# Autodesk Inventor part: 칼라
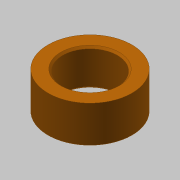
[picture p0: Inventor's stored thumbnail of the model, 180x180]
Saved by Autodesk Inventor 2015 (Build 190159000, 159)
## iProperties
Created: 2015-09
Part Number: 칼라
Document SubType Name: Modeling
Designer: mduedu
Density: 1 g/cm^3
Material: 스테인리스강
Appearance: 주황색
Author: mduedu
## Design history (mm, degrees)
node "작업 평면1"
node "작업 평면2"
sketch "스케치1"
  geometry: C1 r 7.5 at (0, 0); C2 r 11.5 at (0, 0); 1 further point
  constraints: 2 centre point, 2 coincident
  dimensions: "d0" = 15 diameter of C1; "d1" = 23 diameter of C2
extrude "돌출1" new body sketch "스케치1" stored distance "d2" = 9.85; taper "d3" = 0 deg
chamfer "모따기1" distance "d4" = 0.5; stored, may be unused: second distance "d5" = 2, angle "d6" = 45 deg
node "솔리드1"
